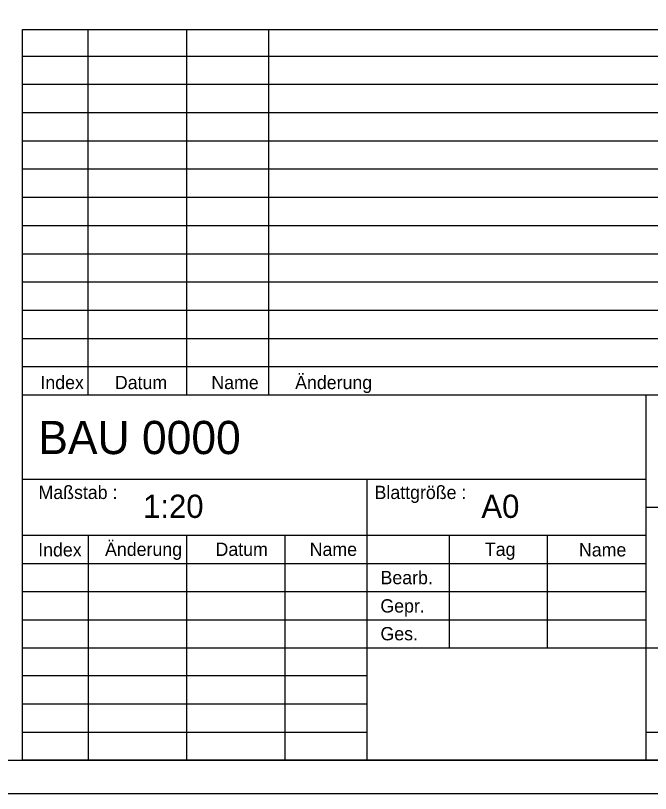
# Model space of a CAD drawing. Extents: x 0 to 23.8, y 0 to 16.8.
# Drawn here: x 20.101 to 22.013, y 0 to 2.342 of the extents above; entities that cross this region are included whole.
import ezdxf

# ---------------------------------------------------------------- set-up
doc = ezdxf.new("R2010")
doc.units = 0
doc.layers.add('90_Plankopf', color=7, linetype='Continuous')

msp = doc.modelspace()

# ---------------------------------------------------------------- linework, layer by layer
at = {"layer": '90_Plankopf'}
for p, q in [((20.1224, 1.1998), (20.1224, 2.2996)), ((20.1224, 2.2996), (23.68, 2.2996)), ((20.32, 1.1998), (20.32, 2.2996)), ((20.6165, 1.1998), (20.6165, 2.2996)), ((20.8636, 1.1998), (20.8636, 2.2996)), ((20.1224, 2.2198), (23.68, 2.2198)), ((20.1224, 2.1348), (23.68, 2.1348)), ((20.1224, 2.0498), (23.68, 2.0498)), ((20.1224, 1.9648), (23.68, 1.9648)), ((20.1224, 1.8798), (23.68, 1.8798)), ((20.1224, 1.7948), (23.68, 1.7948)), ((20.1224, 1.7098), (23.68, 1.7098)), ((20.1224, 1.6248), (23.68, 1.6248)), ((20.1224, 1.5398), (23.68, 1.5398)), ((20.1224, 1.4548), (23.68, 1.4548)), ((20.1224, 1.3698), (23.68, 1.3698)), ((20.1224, 1.2848), (23.68, 1.2848)), ((20.1224, 1.1998), (23.68, 1.1998)), ((20.1224, 0.1), (20.1224, 1.1998)), ((20.1224, 1.1998), (23.68, 1.1998)), ((22, 0.1), (22, 1.1998)), ((20.1224, 0.946), (22, 0.946)), ((21.16, 0.1), (21.16, 0.946)), ((22, 0.8614), (23.68, 0.8614)), ((20.1224, 0.7774), (22, 0.7774)), ((20.32, 0.7768), (20.32, 0.1)), ((20.6165, 0.1), (20.6165, 0.7768)), ((20.913, 0.1), (20.913, 0.7768)), ((21.4071, 0.7768), (21.4071, 0.4384)), ((21.7036, 0.4384), (21.7036, 0.7768)), ((20.1224, 0.6926), (22, 0.6926)), ((20.1224, 0.6076), (22, 0.6076)), ((20.1224, 0.523), (22, 0.523)), ((20.1224, 0.4384), (22, 0.4384)), ((20.1224, 0.4384), (22, 0.4384)), ((21.16, 0.4384), (22, 0.4384)), ((22, 0.4384), (23.68, 0.4384)), ((21.16, 0.3538), (20.1224, 0.3538)), ((21.16, 0.2692), (20.1224, 0.2692)), ((20.1224, 0.1846), (21.16, 0.1846)), ((22, 0.1846), (23.68, 0.1846)), ((23.68, 0.1), (20.1224, 0.1)), ((20.1224, 0.1), (21.16, 0.1)), ((20.356, 0.1), (23.68, 0.1)), ((20.356, 0.1), (23.68, 0.1))]:
    msp.add_line(p, q, dxfattribs=at)
for points in [[(0, 0), (23.78, 0), (23.78, 16.82), (0, 16.82)], [(0.5, 0.1), (23.68, 0.1), (23.68, 16.72), (0.5, 16.72)]]:
    msp.add_lwpolyline(points, close=True, dxfattribs=at)

# ---------------------------------------------------------------- texts
for s, height, p in [('Änderung', 0.04, (20.9431, 1.2171)), ('Index', 0.04, (20.1761, 1.2171)), ('Datum', 0.04, (20.4003, 1.2171)), ('Name', 0.04, (20.6908, 1.2171)), ('BAU 0000      ', 0.1, (20.1698, 1.0215)), ('Maßstab :', 0.04, (20.1703, 0.8863)), ('Blattgröße :', 0.039998, (21.1823, 0.8863)), ('1:20     ', 0.07, (20.4852, 0.8294)), ('A0       ', 0.07, (21.504, 0.8294)), ('Index', 0.04, (20.1694, 0.7135)), ('Änderung', 0.04, (20.3707, 0.715)), ('Datum', 0.04, (20.7034, 0.715)), ('Name', 0.04, (20.9869, 0.715)), ('Tag', 0.04, (21.5145, 0.715)), ('Name', 0.04, (21.7978, 0.7135)), ('Bearb.', 0.04, (21.2003, 0.6298)), ('Gepr.', 0.04, (21.1998, 0.5446)), ('Ges.', 0.04, (21.2001, 0.4609))]:
    msp.add_text(s, height=height, dxfattribs=at).set_placement(p)

doc.saveas('drawing.dxf')
